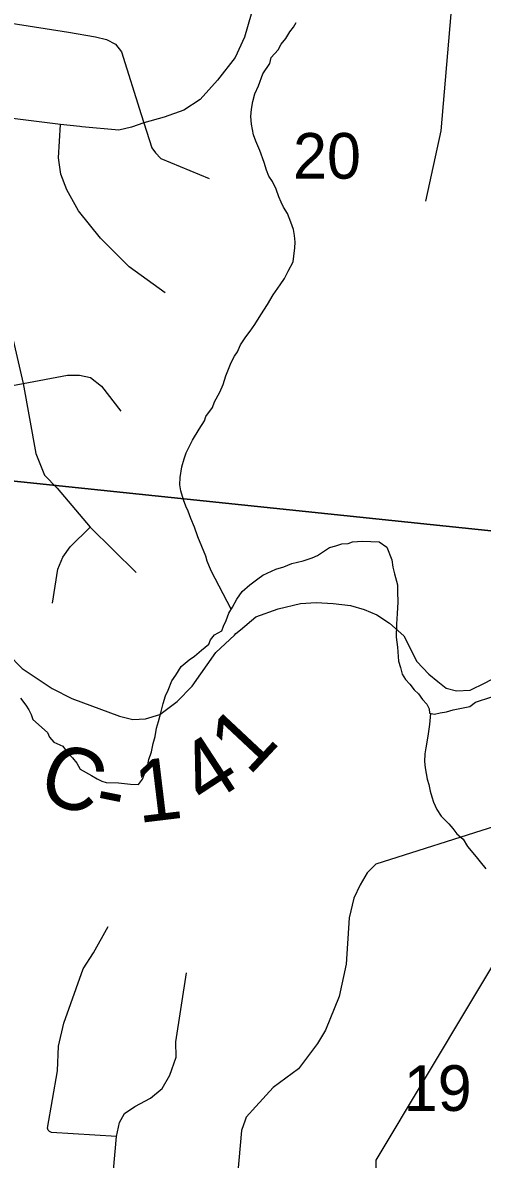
# Model space of a CAD drawing. Extents: x 0 to 43.4, y -8.1 to 22.
# Drawn here: x 6.05 to 6.471, y 17.842 to 18.884 of the extents above; entities that cross this region are included whole.
import ezdxf

# ---------------------------------------------------------------- set-up
doc = ezdxf.new("R2010")
doc.units = 0
for name, color, linetype in [('GM_X_Corporation', 7, 'Continuous'), ('GM_X_County_Road', 7, 'Continuous'), ('GM_X_County_Road_Text', 7, 'Continuous'), ('GM_X_Minor_River', 7, 'Continuous'), ('GM_X_Section_Text', 7, 'Continuous'), ('GM_X_Township_Road', 7, 'Continuous'), ('SH_Text', 7, 'Continuous')]:
    doc.layers.add(name, color=color, linetype=linetype)

msp = doc.modelspace()

# ---------------------------------------------------------------- linework, layer by layer
at = {"layer": 'GM_X_Corporation'}
for points in [[(5.9616, 19.4927), (6.9413, 19.3833), (6.8431, 18.3799), (5.8893, 18.4791)], [(6.8431, 18.3799), (6.7271, 17.3517), (5.7989, 17.456), (5.8893, 18.4791)]]:
    msp.add_lwpolyline(points, close=True, dxfattribs=at)
at = {"layer": 'GM_X_County_Road'}
for points in [[(5.879, 18.4051), (5.8905, 18.3946), (5.9226, 18.367), (5.9442, 18.3493), (5.9637, 18.3387), (6.0009, 18.3279), (6.0136, 18.3227), (6.0245, 18.3163), (6.036, 18.305), (6.0493, 18.2915), (6.0768, 18.2732), (6.0947, 18.2642), (6.1384, 18.2479), (6.1507, 18.2449), (6.1624, 18.2455), (6.1754, 18.2495), (6.1913, 18.2615), (6.2051, 18.2755), (6.2269, 18.3063), (6.2439, 18.3223), (6.2453, 18.3236), (6.2495, 18.3271)], [(6.2495, 18.3271), (6.2636, 18.339), (6.284, 18.3463), (6.3046, 18.3513), (6.319, 18.352), (6.3345, 18.3511), (6.3504, 18.3495), (6.3628, 18.3456), (6.3744, 18.3407), (6.3863, 18.3331), (6.3992, 18.3217), (6.4113, 18.2981), (6.4223, 18.2864), (6.4304, 18.2797), (6.4382, 18.2737), (6.4476, 18.2711), (6.4601, 18.2717), (6.474, 18.2786), (6.5051, 18.295)]]:
    msp.add_lwpolyline(points, dxfattribs=at)
at = {"layer": 'GM_X_Minor_River'}
for points in [[(6.2409, 18.346), (6.2227, 18.381), (6.2188, 18.3899), (6.2178, 18.3945), (6.2139, 18.4034), (6.2105, 18.4123), (6.2073, 18.4211), (6.2038, 18.4292), (6.2014, 18.4358), (6.1993, 18.4404), (6.1972, 18.4462), (6.1948, 18.4546), (6.1939, 18.46), (6.1941, 18.4668), (6.1956, 18.4766), (6.1977, 18.4838), (6.1998, 18.4894), (6.2027, 18.4954), (6.2055, 18.501), (6.2116, 18.511), (6.2164, 18.5185), (6.2177, 18.5226), (6.2237, 18.5308), (6.2257, 18.536), (6.2306, 18.545), (6.2335, 18.5521), (6.2361, 18.56), (6.241, 18.572), (6.2439, 18.578), (6.2467, 18.582), (6.2496, 18.5884), (6.2544, 18.5955), (6.2584, 18.6007), (6.2627, 18.607), (6.268, 18.6159), (6.2744, 18.6252), (6.2796, 18.6341), (6.286, 18.6434), (6.29, 18.649), (6.2933, 18.6557), (6.2978, 18.6643), (6.2983, 18.6696), (6.2993, 18.6772), (6.2995, 18.6825), (6.299, 18.6886), (6.298, 18.6939), (6.2956, 18.7008), (6.2925, 18.7086), (6.2889, 18.7144), (6.2867, 18.719), (6.2846, 18.724), (6.2822, 18.731), (6.2787, 18.7379), (6.2754, 18.743), (6.2733, 18.7484), (6.2713, 18.7553), (6.2671, 18.7665), (6.2636, 18.7749), (6.2615, 18.7807), (6.2596, 18.7907), (6.2591, 18.7975), (6.2597, 18.8043), (6.2607, 18.8115), (6.2625, 18.8183), (6.2661, 18.8258), (6.2699, 18.8367), (6.2763, 18.8463), (6.2777, 18.8516), (6.284, 18.8586), (6.2868, 18.8638), (6.2912, 18.869), (6.2948, 18.8753), (6.298, 18.8794), (6.3004, 18.8839)], [(6.2653, 18.3739), (6.27, 18.3771), (6.282, 18.3828), (6.2892, 18.3848), (6.2966, 18.388), (6.3069, 18.3903), (6.3153, 18.393), (6.32, 18.3952), (6.3312, 18.4024), (6.337, 18.4041), (6.3424, 18.4058), (6.3481, 18.4063), (6.3523, 18.4077), (6.3614, 18.4082), (6.3766, 18.4076), (6.3836, 18.4028), (6.3882, 18.3913), (6.3891, 18.3844), (6.3908, 18.3783), (6.3935, 18.3683), (6.3936, 18.3618), (6.3937, 18.3523), (6.3933, 18.3421), (6.3926, 18.3322), (6.3922, 18.3204), (6.3934, 18.3113), (6.3945, 18.2983), (6.3962, 18.2926), (6.3978, 18.2864), (6.4007, 18.2814), (6.4047, 18.2774), (6.4087, 18.272), (6.4128, 18.2684), (6.4164, 18.2633), (6.4204, 18.259), (6.4226, 18.2548), (6.4228, 18.2506), (6.4273, 18.2497), (6.4327, 18.251), (6.4384, 18.2519), (6.4445, 18.2536), (6.4598, 18.2569), (6.4649, 18.2609), (6.4799, 18.2657)], [(6.0478, 18.2643), (6.0525, 18.2581), (6.0554, 18.2538), (6.0575, 18.2495), (6.0589, 18.2449), (6.0725, 18.2331), (6.0743, 18.2288), (6.0783, 18.2241), (6.0865, 18.2204), (6.0909, 18.2142), (6.0953, 18.2098), (6.0993, 18.2048), (6.1025, 18.1993), (6.1129, 18.1936), (6.1181, 18.1904), (6.1222, 18.1884), (6.1264, 18.1871), (6.1377, 18.1867), (6.1487, 18.1856), (6.1559, 18.1853), (6.1595, 18.1901), (6.1612, 18.1943), (6.164, 18.2002), (6.1654, 18.2082), (6.168, 18.2153), (6.1694, 18.2229), (6.1711, 18.2293), (6.1725, 18.2368), (6.1742, 18.2432), (6.1764, 18.2511), (6.1786, 18.2594), (6.1807, 18.2666), (6.1832, 18.2718), (6.1865, 18.2804), (6.1901, 18.2856), (6.195, 18.2934), (6.2024, 18.2996), (6.2074, 18.3029), (6.2137, 18.3084), (6.2203, 18.3138), (6.222, 18.318), (6.2256, 18.3224), (6.2325, 18.3263), (6.2338, 18.3305), (6.2363, 18.3357), (6.2388, 18.3425), (6.242, 18.3477), (6.2461, 18.3551), (6.2509, 18.3622), (6.2579, 18.3684), (6.2653, 18.3739)], [(6.4238, 18.2504), (6.4228, 18.2403), (6.4213, 18.2297), (6.4194, 18.2188), (6.4185, 18.2135), (6.4182, 18.2063), (6.4188, 18.2005), (6.4207, 18.1902), (6.4221, 18.1852), (6.4234, 18.1791), (6.4251, 18.1741), (6.4264, 18.1691), (6.4296, 18.1625), (6.4336, 18.1563), (6.4406, 18.1492), (6.4442, 18.1449), (6.4478, 18.1402), (6.4537, 18.1351), (6.4577, 18.1285), (6.4657, 18.1191), (6.4693, 18.1144), (6.4744, 18.1081)]]:
    msp.add_lwpolyline(points, dxfattribs=at)
at = {"layer": 'GM_X_Township_Road'}
for points in [[(6.2648, 18.9452), (6.2592, 18.8915), (6.2531, 18.8703), (6.2445, 18.8518), (6.2283, 18.8308), (6.2124, 18.8132), (6.1976, 18.8034), (6.1795, 18.7969), (6.1609, 18.7918), (6.1494, 18.7878), (6.1379, 18.7852), (6.104, 18.7882)], [(6.4455, 18.9278), (6.4332, 18.7844), (6.4192, 18.7199)], [(5.912, 18.9052), (5.973, 18.8999), (5.9843, 18.898), (6.0075, 18.8881), (6.0916, 18.8748), (6.1165, 18.8706), (6.1266, 18.8683), (6.1348, 18.8639), (6.1403, 18.8569), (6.1585, 18.7993), (6.1609, 18.7918), (6.1681, 18.769), (6.1714, 18.7643), (6.1765, 18.7592), (6.2206, 18.7407)], [(6.104, 18.7882), (6.1021, 18.7884), (6.0844, 18.7904), (6.0329, 18.7966), (6.0168, 18.797), (6.0099, 18.7967), (6.0019, 18.7952), (5.9971, 18.7897)], [(6.1804, 18.636), (6.1475, 18.6599), (6.121, 18.6862), (6.101, 18.7111), (6.0901, 18.7305), (6.0847, 18.7446), (6.0824, 18.7596), (6.0844, 18.7904)], [(6.0409, 18.5925), (6.0501, 18.5528), (6.0618, 18.4886), (6.0696, 18.4687), (6.0813, 18.4569), (6.1116, 18.4211), (6.1537, 18.3796)], [(5.9825, 18.4927), (5.9874, 18.53), (5.9918, 18.5378), (6.0025, 18.5441), (6.0501, 18.5528), (6.0908, 18.5604), (6.1019, 18.5606), (6.1118, 18.5584), (6.1221, 18.5505), (6.1398, 18.5276)], [(6.0771, 18.3515), (6.0819, 18.3828), (6.0866, 18.3937), (6.0932, 18.4032), (6.1116, 18.4211)], [(6.4862, 18.1564), (6.4833, 18.1471), (6.3737, 18.1124), (6.3658, 18.1044), (6.3593, 18.0934), (6.3533, 18.081), (6.3491, 18.0632), (6.3465, 18.0205), (6.3401, 17.991), (6.3274, 17.9601), (6.3202, 17.9478), (6.3028, 17.9248), (6.2796, 17.9075), (6.2637, 17.8903), (6.2547, 17.8804), (6.2537, 17.8775)], [(6.1357, 17.8625), (6.076, 17.8664), (6.0742, 17.8672), (6.073, 17.8686), (6.0724, 17.8703), (6.0815, 17.9229), (6.0826, 17.9454), (6.0874, 17.9664), (6.1052, 18.0162), (6.1147, 18.031), (6.1281, 18.055)], [(6.1315, 17.8148), (6.1357, 17.8625), (6.1385, 17.8756), (6.143, 17.8836), (6.1526, 17.8901), (6.1668, 17.8977), (6.1775, 17.9067), (6.1847, 17.9188), (6.1906, 17.9354), (6.1902, 17.9493), (6.1999, 18.0128)], [(6.2537, 17.8775), (6.2505, 17.868), (6.2415, 17.7685), (6.2401, 17.7591)]]:
    msp.add_lwpolyline(points, dxfattribs=at)
at = {"layer": 'SH_Text'}
msp.add_lwpolyline([(6.3738, 17.8409), (6.9134, 18.7404), (6.3738, 17.3215)], close=True, dxfattribs=at)

# ---------------------------------------------------------------- texts
at = {"layer": 'GM_X_County_Road_Text'}
for s, rotation, p in [('1', 46.8807, (6.2573, 18.1922)), ('C', 339.937, (6.061, 18.1737)), ('4', 33.1304, (6.2169, 18.1637)), ('1', 6.8718, (6.1559, 18.1499)), ('-', 348.5189, (6.1135, 18.1553))]:
    msp.add_text(s, height=0.0568, rotation=rotation, dxfattribs=at).set_placement(p)
at = {"layer": 'GM_X_Section_Text'}
for s, p in [('20', (6.2977, 18.7406)), ('19', (6.3993, 17.8861))]:
    msp.add_text(s, height=0.04186, rotation=0, dxfattribs=at).set_placement(p)

doc.saveas('drawing.dxf')
